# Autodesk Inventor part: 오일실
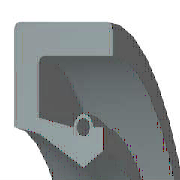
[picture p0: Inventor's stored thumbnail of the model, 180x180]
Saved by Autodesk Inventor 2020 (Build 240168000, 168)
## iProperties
IsCustomPart: 0
Created: 2009-02
Part Number: 오일실
Material: 고무
Description: 오일-실
Document SubType Name: Modeling
Standard: KS B 2804
Standards Organization: KS
Language: ko-KR
Size Designation: S - 17 30 8
Categories: <MemberInstance><Categories><Category DisplayName="샤프트 부품" InternalName="7f7aeb1f-a693-4053-b835-cee3144e0d98" Mnemonic="SHFT"><Category DisplayName="실링" Intern
Density: 0.93 g/cm^3
Appearance: 고무 - 검은색 - 버전 1.1
Author: pww
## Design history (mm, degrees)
revolve "본체" stored, may be unused: angle "d17" = 90 deg
revolve "스프링1" stored, may be unused: angle "d18" = 90 deg
body "Solid1"
sketch "스케치1"
  geometry: L1 (0, 15)-(8, 15); L2 (8, 15)-(8, 13.75); L3 (8, 13.75)-(1.75, 13.75); L4 (0, 15)-(0, 10.6); L5 (0, 10.6)-(1.75, 10.25); L6 (1.75, 10.25)-(4.9, 8.5); L7 (4.9, 8.5)-(0, 8.5); L8 (6.3, 9.375)-(6.3, 10.6); L9 (0, 0)-(9.586, 0) reference; L10 (4.9, 8.5)-(6.3, 9.375); L11 (0, 18)-(0, -3) reference; L12 (-1.917, 0)-(11.503, 0) reference; L13 (4.2, 10.6)-(1.75, 11.09); L14 (1.75, 11.09)-(1.75, 13.75); L15 (6.3, 10.6)-(5.6, 10.6); C1 r 0.455 at (4.9, 10.6); A1 r 0.7 centre (4.9, 10.6) between (5.6, 10.6) and (4.2, 10.6)
  constraints: 26 end point, 5 horizontal alignment, 4 perpendicular, 2 centre point, 2 collinear, 2 horizontal, 2 parallel, 2 point on circle, 2 point on line, 2 vertical alignment, 1 coincident
  dimensions: "d0" = 30 diameter of L1 L9 (= SD2); "d1" = 18.75 diameter of L8.start L9 (= ABDM); "d2" = 1.25 distance of L1.end L2.end (computed from SD); "d3" = 0.91 diameter of C1 (= SPDI); "d4" = 1.4 diameter of A1 (= SPDA); "d5" = 17 diameter of L6.end L9 (= NND); "d6" = 20.5 diameter of L5.end L9 (= TKDM); "d7" = 21.2 diameter of L4.end L9 (= HLDM); "d8" = 4.9 distance from line of C1.centre L4 (= SPDST); "d9" = 6.3 distance between parallel lines of L8 L4 (= SDI); "d10" = 8 distance between parallel lines of L2 L4 (= SWDT); "d12" = 1.75 distance between parallel lines of L14 L4 (= SD)
fillet "모깎기1" dims "d11" = 0.3 (= RR)
other parameters: "SD2" = 30 [user parameter; used in 1 equation term], "SWDT" = 8 [user parameter; used in 1 equation term], "RR" = 0.3 [user parameter; used in 1 equation term], "SD" = 1.75 [user parameter; used in 2 equation terms], "NND" = 17 [user parameter; used in 1 equation term], "SPDA" = 1.4 [user parameter; used in 1 equation term], "SPDI" = 0.91 [user parameter; used in 1 equation term], "TKDM" = 20.5 [user parameter; used in 1 equation term], "HLDM" = 21.2 [user parameter; used in 1 equation term], "ABDM" = 18.75 [user parameter; used in 1 equation term], "SDI" = 6.3 [user parameter; used in 1 equation term], "SPDST" = 4.9 [user parameter; used in 1 equation term], "d13" = 0, "d14" = 0, "d15" = 0, "LAB" = 0.35 [user parameter]
